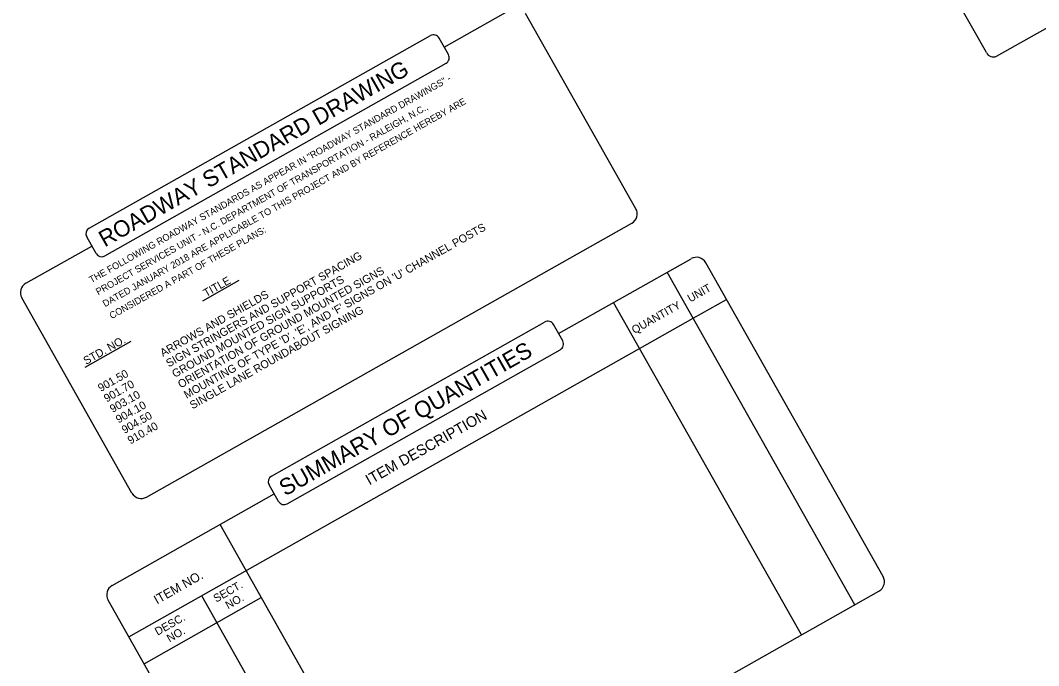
# Model space of a CAD drawing. Extents: x 2217708 to 2219063, y 217550 to 219141.
# Drawn here: x 2217708 to 2218553, y 217935 to 218471 of the extents above; entities that cross this region are included whole.
import ezdxf

# ---------------------------------------------------------------- set-up
doc = ezdxf.new("R2010")
doc.units = 0
for name, color, linetype in [('Default', 7, 'Continuous'), ('DEV TITLE SHEET CELL', 7, 'Continuous'), ('Sheet Title CELL', 7, 'Continuous')]:
    doc.layers.add(name, color=color, linetype=linetype)

msp = doc.modelspace()

# ---------------------------------------------------------------- linework, layer by layer
at = {"layer": 'Default'}
for p, q in [((2218400.22, 217985.52), (2218244.6, 218261.67)), ((2217859.43, 218237.98), (2217889.56, 218255)), ((2218356.08, 217960.59), (2218200.12, 218236.6)), ((2218266.14, 218223.45), (2218293.81, 218239.09)), ((2218221.74, 218198.34), (2218266.14, 218223.45)), ((2217761.74, 218182.79), (2217799.96, 218204.37)), ((2217798.09, 217958.82), (2218221.74, 218198.34)), ((2218029.66, 217776.18), (2217873.69, 218052.11)), ((2217810.67, 217936.54), (2217907.93, 217991.53)), ((2217992.87, 217755.41), (2217858.54, 217992.99)), ((2217871, 217971.94), (2217871, 217971.94))]:
    msp.add_line(p, q, dxfattribs=at)
at = {"layer": 'Sheet Title CELL'}
for p, q in [((2218509.56, 218443.96), (2218407.69, 218624.46)), ((2218517.9, 218441), (2218819.79, 218611.5)), ((2218059.73, 218448.51), (2218115.09, 218479.78)), ((2218218.67, 218314.38), (2218127.23, 218476.4)), ((2218063.21, 218442.35), (2218055.49, 218456.03)), ((2217812.78, 218074.91), (2218215.3, 218302.24)), ((2217770.8, 218277.2), (2217763.07, 218290.88)), ((2217712.57, 218252.44), (2217767.32, 218283.36)), ((2218154.45, 218210.85), (2218264.49, 218272.88)), ((2218423.75, 218009.03), (2218276.63, 218269.51)), ((2217800.64, 218078.28), (2217709.19, 218240.3)), ((2218157.99, 218204.57), (2218150.27, 218218.25)), ((2217922.14, 218071.4), (2217914.41, 218085.08)), ((2217784.18, 218001.56), (2217918.68, 218077.52)), ((2217940.05, 217725.57), (2218420.37, 217996.89)), ((2217927.91, 217728.95), (2217780.8, 217989.42))]:
    msp.add_line(p, q, dxfattribs=at)
for points in [[(2217765.1, 218298.16), (2218048.2, 218458.05)], [(2217778.08, 218275.17), (2218061.18, 218435.07)], [(2217916.44, 218092.36), (2218142.98, 218220.28)], [(2217929.42, 218069.37), (2218155.97, 218197.29)]]:
    msp.add_lwpolyline(points, dxfattribs=at)
for centre, radius, start, end in [((2218050.83, 218453.4), 5.35, 29.45694, 119.45694), ((2218058.56, 218439.72), 5.35, 299.45694, 29.45694), ((2218515.21, 218446.65), 6.26, 205.48311, 295.48311), ((2218210.92, 218310), 8.91, 299.45694, 29.45694), ((2217767.73, 218293.51), 5.35, 119.45694, 209.45694), ((2217775.45, 218279.83), 5.35, 209.45694, 299.45694), ((2218268.88, 218265.13), 8.91, 29.45694, 119.45694), ((2217716.95, 218244.68), 8.91, 119.45694, 209.45694), ((2218145.61, 218215.62), 5.35, 29.45694, 119.45694), ((2218153.34, 218201.94), 5.35, 299.45694, 29.45694), ((2217919.07, 218087.71), 5.35, 119.45694, 209.45694), ((2217808.4, 218082.67), 8.91, 209.45694, 299.45694), ((2217926.79, 218074.03), 5.35, 209.45694, 299.45694), ((2218415.99, 218004.65), 8.91, 299.45694, 29.45694), ((2217788.56, 217993.81), 8.91, 119.45694, 209.45694)]:
    msp.add_arc(centre, radius, start, end, dxfattribs=at)

# ---------------------------------------------------------------- texts
at = {"layer": 'Default'}
for s, height, rotation, p in [('ROADWAY STANDARD DRAWING', 13.5942, 29.63919, (2217778.04, 218282.13)), ("904.50             MOUNTING OF TYPE 'D', 'E', AND 'F' SIGNS ON 'U' CHANNEL POSTS", 6.6381, 29.45694, (2217794.43, 218127.29)), ('901.70             SIGN STRINGERS AND SUPPORT SPACING', 6.6381, 29.45694, (2217779.66, 218153.41)), ('904.10             ORIENTATION OF GROUND MOUNTED SIGNS', 6.6381, 29.45694, (2217789.5, 218136)), ('903.10             GROUND MOUNTED SIGN SUPPORTS', 6.6381, 29.45694, (2217784.58, 218144.7)), ('TITLE', 6.638, 29.45694, (2217862.18, 218240.85)), ('901.50             ARROWS AND SHIELDS', 6.6381, 29.45694, (2217774.74, 218162.11)), ('UNIT', 6.638, 29.48353, (2218263.84, 218236.41)), ('QUANTITY', 6.638, 29.48353, (2218217.49, 218210.2)), ('910.40             SINGLE LANE ROUNDABOUT SIGNING', 6.6381, 29.45694, (2217799.35, 218118.59)), ('STD. NO.', 6.638, 29.45694, (2217762.6, 218184.59)), ('SUMMARY OF QUANTITIES', 13.5942, 29.63919, (2217927.71, 218075.37)), ('ITEM DESCRIPTION', 8.91, 29.48353, (2217997.57, 218084.55)), ('ITEM NO.', 7.573, 29.48353, (2217821.39, 217985.71)), ('SECT.', 6.638, 29.48353, (2217870.52, 217987.25)), ('NO.', 6.638, 29.48353, (2217880.41, 217981.69)), ('DESC.', 6.638, 29.48353, (2217821.89, 217959.76)), ('NO.', 6.638, 29.48353, (2217831.78, 217954.19))]:
    msp.add_text(s, height=height, rotation=rotation, dxfattribs=at).set_placement(p)
at = {"layer": 'DEV TITLE SHEET CELL'}
for s, p in [('THE FOLLOWING ROADWAY STANDARDS AS APPEAR IN "ROADWAY STANDARD DRAWINGS" -', (2217767, 218252.46)), ('DATED JANUARY 2018 ARE APPLICABLE TO THIS PROJECT AND BY REFERENCE HEREBY ARE ', (2217778.23, 218232.55)), ('PROJECT SERVICES UNIT - N.C. DEPARTMENT OF TRANSPORTATION - RALEIGH, N.C.,', (2217772.61, 218242.51)), ('CONSIDERED A PART OF THESE PLANS:', (2217783.84, 218222.6))]:
    msp.add_text(s, height=5.6133, rotation=29.41674, dxfattribs=at).set_placement(p)

doc.saveas('drawing.dxf')
